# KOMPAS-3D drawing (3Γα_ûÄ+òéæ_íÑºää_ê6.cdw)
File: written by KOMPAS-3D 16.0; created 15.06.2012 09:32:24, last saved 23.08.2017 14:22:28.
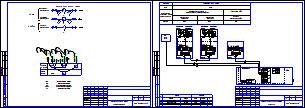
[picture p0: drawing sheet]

Sheets 1-2: A3, landscape

Title block, sheet 1: name: Руководство по эксплуатации; sheet number: 1; sheets: 27; organisation: ООО"Интелприбор"; sheet format: A3; stored path: W:\Users\smirnov_v\Desktop\шаблоны\4-х трубка\4-х трубка ГВС-max.cdw / D:\Проекты\Лыткарино\ул. Квартал 3А, д.25\710.74 РП.cdw; file name: 4-х трубка ГВС-max.cdw / 710.74 РП.cdw; cell 51: МО, Воскресенсикй р-н, п. Хорлово, ул. Интернациональная, д. 4; cell 320: Р
Title block, sheet 2: sheet number: 2

Views: Вид 2, Вид 3
Referenced files in C:\Program Files (x86)\ASCON\KOMPAS-3D V16\Sys\: spds.lcs, EngSys.lcs, GRAPHIC.LHS
Referenced files: graphic.tdp
Referenced files in W:\Users\smirnov_v\Desktop\шаблоны\4-х трубка\: 4-х трубка ГВС-max.cdw
Referenced files in D:\Проекты\Лыткарино\ул. Квартал 3А, д.25\: 710.74 РП.cdw
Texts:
  Смирнов В.С.
  УУ-3423
  GOST Common
  Normal
  List Paragraph
  heading 3
  для схемы
  txt
  Т0-элементы
  Плата подключений
  СБ МКТС
  ВРУ
  каб.
  Начало
  трассы
  Трассы
  Марка
  Проложен
  Изм. модуль (Т1)
  Изм. модуль (Т2)
  Изм. модуль (В1)
  ВРУ 220В, 50 Гц
  ИМ (Т1)
  FTP
  ПВС
  Конец
  Кол-во и
  сеч. жил
  Длина,
  Преобразователь расхода
  Термопреобразователь
  Преобразователь давления
  Преобразователь цифровой
  Системный блок МКТС
  приборы
  по месту
  шкаф
  учета
  UQIES
  Подающий
  трубопровод
  Обратный
  УУТЭ
  Функциональная схема
  Вводной
  УУХВС
  Агрегат
  Системный блок  МКТС
  Среда
  Вода
  параметра и место
  отбора импульса
  Учет тепловой энергии и
  теплоносителя системы отопления
  отопления
  Узел учета ХВС
  трубопровод ХВС
  ИМ1
  ИМ2
  ИМ3
  UP+
  UP-
  ИМП
  Лин
  Измерительный
  модуль М121
  Pt 100
  Преобразователь
  температуры
  давления
  Размеры, параметризация
  сит. план
  подача ГВС
  обратка ГВС
  хвс
  обратка
  POLYLINE_STYLE_0.25_RGB_0_0_0
  стены
  Основная (не является границей для штриховки)
  POLYLINE_STYLE_0.18_RGB_0_0_0
  ХВС
  зеленая
  Красная тонкая
  арматура
  Подача
  Скрытая линия
  Ось Z
  Ось Y
  Ось X
  Образующая трубопровода (проектируемого)
  Трубопровод толщиной 0.6мм (одна линия)
  Трубопровод толщиной 1.2мм (одна линия)
  Трубопровод толщиной 1.0мм (одна линия)
  Трубопровод толщиной 0.8мм (одна линия)
  Трубопровод существующий (одна линия)
  Трубопровод невидимый (одна линия)
  Трубопровод демонтируемый (одна линия)
  Осевая трубопровода
  Осевая трубопровода (демонтируемого)
  Образующая трубопровода (существующего)
  Образующая трубопровода (невидимого)
  Изолированный трубопровод проектируемый (одна линия)
  Изолированный трубопровод существующий (одна линия)
  Образующая изоляции
  Изоляция
  Изолированный трубопровод невидимый (одна линия)
  Штрих пвс 075
  штрих пвс 2,5
  существующее оборудование
  Существующее оборудование
  K5LT_BASIC_RGB_0_0_255_THICK_0.53
  POLYLINE_STYLE_1.51_RGB_0_0_255
  POLYLINE_STYLE_0.50_RGB_128_128_128
  K5LT_AXLED_RGB_255_128_0_SC_1_THICK_0.18
  ACAD_ISO04W100_RGB_0_0_0_SC_1_THICK_0.18
  тонкая черная
  тонкая красная
  тонкая синяя
  тонкая оранж
  красн штрих
  пломбировка
  Провода
  синий штрих
  Стили документа
  G2co
  расход вторичной воды объемный
  расход вторичной воды объемный при 70гр
  Gco
  расход теплоносителя массовый
  расход теплоносит объемн подающ
  расход теплоносит объемн обр
  Лапир
  Ghvs
  Im1
  Im2
  Im3
  Im4
  Im5
  Khvs
  норматив ХВС
  число подъездов
  число этажей
  Nkv
  число квартир
  тепловая нагрузка на отопление
  сумма Q
  Qgvs
  тепловая нагрузка ГВС
  тепловая нагрузка на циркуляцию ГВС
  иммитовставка или под манометр
  ro1
  ro2
  ro3
  ro4
  верх предел темп граф
  нижн предел темп граф
  темп подачи ГВС
  темп обр ГВС
  темр хол воды
  vzdh
  Kchn
  Ktp
  Knp
  tnv
  Vклап
  KLP
  RPD
  RDS
  PUMP
  ro5
  beta
  tnv98
  Shifr
  Переход ГОСТ 17378-2001
  Переход
  ГОСТ
  Сталь 09Г2С ГОСТ 19281-89
  Втулка 20x50
  Лит-Масса-Масштаб
  Материал-Предприятие
  Title Specification
  Body Specification ( left align )
  Body Specificaton ( centered )
  Поз.
  Кол.
  Приме-
  чание
  Таблица спецификации
  Засыпка
  Штрих3
  Штрих2
  Штрих1
  Песок
  Штр0.5пр7
  Штр0.5пр12
  Штр0.3пр10
  Штр1.4пр21.21
  Штр1пр15
  Штр2.12пр35
  Штр1.5пр25
  Штр2.82пр42.42
  Штр2пр30
  SACNCR_ISO 1
  Электрощитовая
  Пр-1
  Ок-1
  Обозначение стандарта
  Типоразмер
  Пояснительная записка
  автоматизации
  Рабочие чертежи основного комплекта. ГОСТ Р 21.1101-2009 Ф3
  Стадия
  Лист
  Листов
  Изм.
  Кол.уч.
  №док.
  Подп.
  Дата
  Разраб.
  Пров.
  Т.контр.
  Н.контр.
  Утв.
  Изменение
  Номер документа
  Подпись
  Наименование объекта строительства, в состав которого входит здание, наим. микр
  Наименование здания (сооружения)
  Порядковый номер листа
  Количество листов в документе
  Наименование изображения
  Индекс предприятия, выпускающего документ
  Инв. № подл.
  Подп. и дата
  Взам. инв. №
  Инвентарный номер подлинника
  Подпись принявшего подлинник на хранение
  Инвентарный номер подлинника, взамен которого выпущен данный подлинник
  Согласовано
  Формат листа
  Согласование
  03 Рабочие чертежи основного комплекта. ГОСТ Р 21.1101-2009 Ф3
  Схема соединений внешних
  проводок
Dimensions and other numbers on the sheet: 1; 2; 3; 6; 5; 4; 220В; 50Гц; 2x2x0,52; 3х0,75; 0; 11; 1,2,3; 4,5; 6,7; 8,9,10; 7; 8; 9; 10; 5,0; 3,2388; 0,0400; 40; 95; 3,1876; 70; 0,0000; 4-20; 09Г2С; 20; 27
